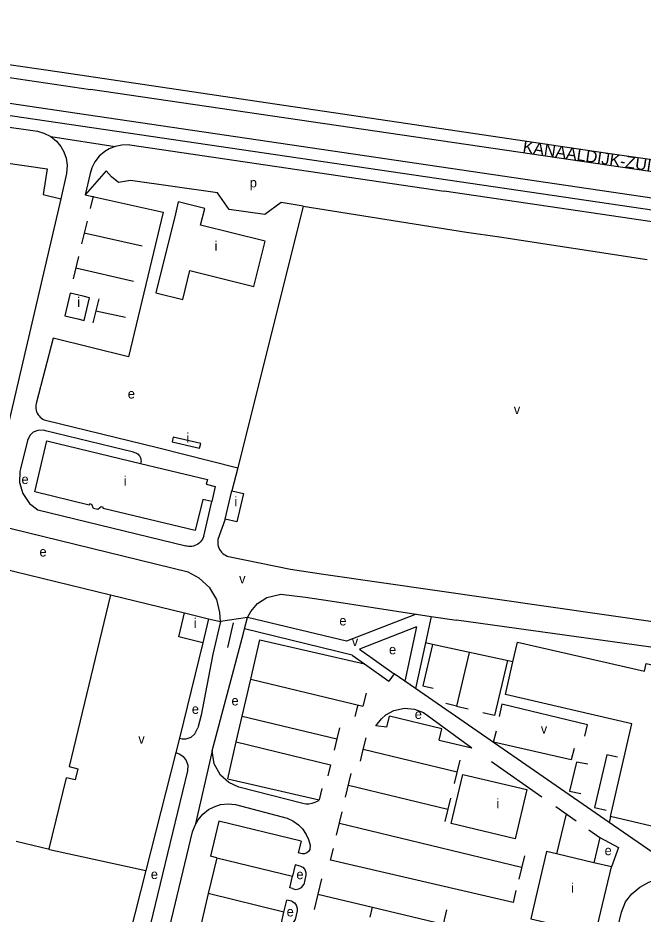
# Model space of a CAD drawing. Extents: x 162804 to 165059, y 381530 to 382901.
# Drawn here: x 163506.9 to 163766.6, y 382442.3 to 382814.6 of the extents above; entities that cross this region are included whole.
import ezdxf

# ---------------------------------------------------------------- set-up
doc = ezdxf.new("R2010")
doc.units = 0
for name, color, linetype in [('BLT_Basislijn', 7, 'Continuous'), ('BLT_Bebouwing', 7, 'Continuous'), ('BLT_Centroide', 7, 'Continuous'), ('BLT_Straatnaam', 7, 'Continuous'), ('BLT_Vlakafsluiter', 7, 'Continuous')]:
    doc.layers.add(name, color=color, linetype=linetype)

msp = doc.modelspace()

# ---------------------------------------------------------------- linework, layer by layer
at = {"layer": 'BLT_Basislijn'}
for p, q in [((163525.18, 382791.94), (163463.22, 382801.03)), ((163609.95, 382779.38), (163525.18, 382791.94)), ((163439.97, 382778.56), (163515.12, 382767.51)), ((163650.18, 382773.33), (163609.95, 382779.38)), ((163750, 382758.53), (163650.18, 382773.33)), ((163798.44, 382751.58), (163750, 382758.53)), ((163527.16, 382750), (163524.73, 382739.51)), ((163534.85, 382741.17), (163567.22, 382733.85)), ((163538.13, 382740.55), (163536.93, 382735.42)), ((163625.48, 382736.46), (163598.22, 382627.68)), ((163625.48, 382736.46), (163693.25, 382725.64)), ((163535.66, 382730.15), (163533.34, 382720.8)), ((163534.49, 382725.39), (163558.55, 382719.89)), ((163693.25, 382725.64), (163706.93, 382723.66)), ((163706.93, 382723.66), (163768.26, 382714.19)), ((163532.1, 382715.56), (163529.83, 382706.23)), ((163530.95, 382710.74), (163555, 382705.24)), ((163540.51, 382697.97), (163538.09, 382688.01)), ((163539.31, 382692.98), (163551.59, 382690.33)), ((163554.89, 382634.16), (163518.44, 382643.14)), ((163598.22, 382627.68), (163595.84, 382618.18)), ((163584.1, 382599.35), (163587.43, 382613.67)), ((163515.15, 382610.27), (163576.65, 382595.26)), ((163592.95, 382606.41), (163590.01, 382597.94)), ((163545.42, 382574.98), (163576.16, 382567.42)), ((163601.11, 382560.76), (163602.29, 382565.55)), ((163643.38, 382555.68), (163602.29, 382565.55)), ((163672.39, 382566.95), (163643.38, 382555.68)), ((163672.39, 382566.95), (163678.57, 382566)), ((163678.57, 382566), (163676.18, 382554.98)), ((163596.28, 382563.26), (163593.96, 382553.14)), ((163672.5, 382561.63), (163648.81, 382552.42)), ((163672.5, 382561.63), (163667.6, 382539.06)), ((163645.83, 382549.94), (163601.11, 382560.76)), ((163583.67, 382555.06), (163574.03, 382515.44)), ((163603.61, 382539.97), (163607.35, 382556.3)), ((163607.35, 382556.3), (163650.87, 382546.33)), ((163676.18, 382554.98), (163672.05, 382535.98)), ((163679.13, 382554.34), (163675.08, 382537.16)), ((163679.13, 382554.34), (163676.18, 382554.98)), ((163712.52, 382547.09), (163679.13, 382554.34)), ((163645.83, 382549.94), (163650.87, 382546.33)), ((163648.81, 382552.42), (163663.24, 382542.07)), ((163650.87, 382546.33), (163660.95, 382539.1)), ((163600.07, 382524.51), (163603.61, 382539.97)), ((163603.61, 382539.97), (163650.25, 382528.69)), ((163667.6, 382539.06), (163663.24, 382542.07)), ((163672.05, 382535.98), (163667.6, 382539.06)), ((163675.08, 382537.16), (163679.48, 382536.21)), ((163651.55, 382534.06), (163650.25, 382528.69)), ((163648.11, 382529.2), (163646.94, 382524.36)), ((163689.13, 382528.73), (163684.68, 382529.84)), ((163582.98, 382525.03), (163581.69, 382519.69)), ((163597.63, 382513.84), (163600.07, 382524.51)), ((163600.07, 382524.51), (163639.42, 382515.07)), ((163660.1, 382519.92), (163661.22, 382524.54)), ((163683.08, 382519.25), (163661.22, 382524.54)), ((163660.1, 382519.92), (163655.61, 382520.59)), ((163640.54, 382519.73), (163639.42, 382515.07)), ((163681.96, 382514.63), (163683.08, 382519.25)), ((163594.11, 382498.48), (163597.63, 382513.84)), ((163597.63, 382513.84), (163636.82, 382504.35)), ((163639.42, 382515.07), (163638.29, 382510.42)), ((163650.39, 382510.74), (163651.56, 382515.6)), ((163681.96, 382514.63), (163695.43, 382511.37)), ((163572.49, 382509.41), (163560.07, 382460.39)), ((163649.21, 382505.88), (163650.39, 382510.74)), ((163689.36, 382501.3), (163650.39, 382510.74)), ((163688.21, 382496.56), (163690.56, 382506.28)), ((163577.41, 382501.87), (163567, 382458.87)), ((163636.82, 382504.35), (163635.7, 382499.7)), ((163594.11, 382498.48), (163632.09, 382489.79)), ((163643.05, 382490.95), (163645.4, 382500.67)), ((163633.22, 382494.44), (163632.09, 382489.79)), ((163685.55, 382485.81), (163644.22, 382495.81)), ((163684.34, 382480.79), (163686.69, 382490.51)), ((163586.1, 382485.73), (163588.48, 382486.95)), ((163588.48, 382486.95), (163591.09, 382487.8)), ((163591.09, 382487.8), (163594.26, 382488.12)), ((163594.26, 382488.12), (163597.26, 382487.83)), ((163597.26, 382487.83), (163618.81, 382482.14)), ((163581.74, 382481.5), (163583.7, 382483.78)), ((163583.7, 382483.78), (163586.1, 382485.73)), ((163639.28, 382475.13), (163641.64, 382484.85)), ((163734.61, 382484.01), (163730.68, 382467.32)), ((163753.09, 382482.83), (163752.54, 382480.4)), ((163579.5, 382476.48), (163580.53, 382479.33)), ((163580.53, 382479.33), (163581.74, 382481.5)), ((163590.42, 382480.95), (163586.91, 382466.36)), ((163624.53, 382472.66), (163590.42, 382480.95)), ((163618.81, 382482.14), (163621.1, 382481.11)), ((163621.1, 382481.11), (163623.52, 382479.36)), ((163623.52, 382479.36), (163625.14, 382477.7)), ((163716.15, 382461.67), (163640.46, 382479.99)), ((163558.92, 382390.87), (163579.5, 382476.48)), ((163625.14, 382477.7), (163626.65, 382475.39)), ((163626.65, 382475.39), (163627.6, 382473.38)), ((163624.53, 382472.66), (163623.35, 382467.73)), ((163627.6, 382473.38), (163628.34, 382471.02)), ((163748.68, 382474.15), (163746.21, 382463.66)), ((163520.03, 382469.15), (163560.07, 382460.39)), ((163628.34, 382471.02), (163628.16, 382469.17)), ((163636.77, 382464.75), (163637.95, 382469.61)), ((163589.53, 382465.72), (163585.95, 382450.81)), ((163589.53, 382465.72), (163586.91, 382466.36)), ((163589.53, 382465.72), (163621.03, 382458.1)), ((163625.02, 382467.32), (163623.35, 382467.73)), ((163717.32, 382466.53), (163714.97, 382456.81)), ((163560.07, 382460.39), (163545.33, 382402.23)), ((163622.15, 382462.75), (163621.03, 382458.1)), ((163624.14, 382462.27), (163622.15, 382462.75)), ((163567, 382458.87), (163555.83, 382412.66)), ((163619.85, 382453.2), (163621.03, 382458.1)), ((163626.48, 382458.45), (163625.62, 382454.59)), ((163621.01, 382452.92), (163619.85, 382453.2)), ((163585.95, 382450.81), (163582.61, 382436.52)), ((163617.39, 382443.16), (163585.95, 382450.81)), ((163631.52, 382450.59), (163654.21, 382445.19)), ((163713.82, 382452.06), (163712.64, 382447.2)), ((163617.39, 382443.16), (163618.64, 382448.16)), ((163620.76, 382447.72), (163618.64, 382448.16)), ((163653.23, 382441.11), (163654.21, 382445.19))]:
    msp.add_line(p, q, dxfattribs=at)
for points in [[(163350, 382814.61), (163413.51, 382803.18), (163537.13, 382784.9)], [(163993.07, 382706.91), (163535.27, 382774.35), (163455.47, 382786.14), (163410.94, 382792.86), (163374.85, 382798.03), (163359.37, 382797.83)], [(164235.25, 382681.52), (163993.98, 382717.68), (163844.23, 382739.9), (163537.13, 382784.9)], [(163666.72, 382750), (163500, 382774.52)], [(163425.36, 382769.97), (163425.25, 382768.68), (163425.6, 382767.33), (163426.26, 382766.16), (163427.26, 382765.28), (163519.12, 382751.86), (163517.34, 382741.19), (163524.73, 382739.51)], [(163515.12, 382767.51), (163517.69, 382766.8), (163520.61, 382765.32)], [(163520.61, 382765.32), (163522.91, 382763.42), (163524.71, 382761.21), (163525.98, 382759.02), (163527, 382756.31), (163527.41, 382753.45), (163527.16, 382750)], [(163547.37, 382761.26), (163544.78, 382760.19), (163542.96, 382759.11), (163540.72, 382757.13), (163538.86, 382754.8), (163537.66, 382752.34), (163536.9, 382750), (163534.85, 382741.17)], [(163553.4, 382761.82), (163550.1, 382761.72), (163547.37, 382761.26)], [(163553.4, 382761.82), (163683.99, 382742.6)], [(163625.48, 382736.46), (163616.32, 382737.96), (163609.51, 382732.91), (163594.68, 382735.09), (163589.79, 382741.9), (163553.67, 382747.12), (163548.67, 382746.2), (163545.83, 382748.56), (163543.55, 382751.15), (163534.85, 382741.17)], [(163844.57, 382723.84), (163833.36, 382725.49), (163666.72, 382750)], [(163843.88, 382719.02), (163800.44, 382725.41), (163683.99, 382742.6)], [(163524.73, 382739.51), (163499.07, 382630.19), (163498.36, 382627.64), (163497.09, 382625.15)], [(163567.22, 382733.85), (163552.83, 382673.88), (163521.57, 382681.64), (163514.65, 382655.01)], [(163514.65, 382655.01), (163514.46, 382654.36), (163514.34, 382653.69), (163514.3, 382653.01), (163514.34, 382652.33), (163514.46, 382651.66), (163514.65, 382651), (163514.92, 382650.38), (163515.27, 382649.79), (163515.68, 382649.25), (163516.15, 382648.75), (163516.67, 382648.32), (163517.25, 382647.95), (163517.86, 382647.65), (163518.42, 382647.45)], [(163518.42, 382647.45), (163564.95, 382636.11), (163598.22, 382627.68)], [(163518.44, 382643.14), (163517.49, 382643.4), (163515.22, 382643.27), (163513.32, 382642.53), (163511.85, 382641.11), (163510.84, 382639.07), (163508.01, 382627.24), (163507.75, 382626.17), (163507.62, 382621.68), (163508.98, 382617.07), (163511.76, 382612.87), (163515.15, 382610.27)], [(163554.89, 382634.16), (163555.41, 382634.07), (163555.91, 382633.9), (163556.39, 382633.66), (163556.82, 382633.35), (163557.19, 382632.98), (163557.51, 382632.55), (163557.76, 382632.09), (163557.94, 382631.59), (163558.04, 382631.06), (163558.06, 382630.54), (163558, 382630.01), (163557.89, 382629.56)], [(163591.01, 382563.83), (163590.81, 382567.55), (163589.61, 382572.98), (163586.59, 382577.82), (163582.17, 382581.94), (163577.59, 382584.32), (163450.78, 382615.36)], [(163584.1, 382599.35), (163583.87, 382598.7), (163583.56, 382598.07), (163583.18, 382597.49), (163582.74, 382596.96), (163582.24, 382596.48), (163581.68, 382596.05), (163581.09, 382595.7), (163580.45, 382595.42), (163579.79, 382595.21), (163579.11, 382595.08), (163578.42, 382595.03), (163577.72, 382595.06), (163577.04, 382595.16), (163576.65, 382595.26)], [(163590.01, 382597.94), (163589.93, 382597.23), (163589.93, 382596.53), (163590.01, 382595.82), (163590.17, 382595.13), (163590.4, 382594.46), (163590.71, 382593.82), (163591.09, 382593.22), (163591.54, 382592.67), (163592.04, 382592.17), (163592.6, 382591.73), (163593.2, 382591.36), (163593.84, 382591.05), (163594.36, 382590.87)], [(163594.36, 382590.87), (163620.21, 382585.6), (163633.84, 382583.51), (163820.83, 382556.63)], [(163602.29, 382565.55), (163603.67, 382568.07), (163606.39, 382571.37), (163610.33, 382573.84), (163616.08, 382575.17), (163626.34, 382573.94), (163636.6, 382572.42), (163672.39, 382566.95)], [(163586.08, 382565.02), (163591.01, 382563.83)], [(163678.57, 382566), (163689.05, 382564.4)], [(163591.01, 382563.83), (163587.87, 382550.25), (163582.98, 382525.03)], [(163822.79, 382542.39), (163818.73, 382546.46), (163689.05, 382564.4)], [(163587.65, 382510.12), (163600.65, 382559.06), (163601.11, 382560.76)], [(163694.39, 382551.02), (163689.13, 382528.73), (163693.97, 382527.54)], [(163710.35, 382547.61), (163704.91, 382524.85), (163700.04, 382525.97)], [(163663.24, 382542.07), (163660.95, 382539.1)], [(163752.54, 382480.4), (163672.05, 382535.98)], [(163655.61, 382520.59), (163657.97, 382523.42), (163659.8, 382525.09), (163663.11, 382526.87), (163667.46, 382527.85), (163671.68, 382527.5), (163675.4, 382526.02), (163695.43, 382511.37)], [(163742.42, 382516.18), (163743.54, 382520.95), (163707.91, 382529.52), (163706.8, 382524.43)], [(163574.03, 382515.44), (163575.15, 382515.18), (163576.84, 382515.17), (163578.87, 382515.86), (163580.38, 382517.16), (163581.69, 382519.69)], [(163737.98, 382511.14), (163736.79, 382506.36), (163704.52, 382513.7), (163705.76, 382518.48)], [(163572.49, 382509.41), (163574.24, 382508.75), (163575.54, 382507.83), (163576.84, 382506.15), (163577.49, 382504.22), (163577.41, 382501.87)], [(163630.24, 382488.65), (163629.08, 382488.25), (163627.75, 382488.02), (163626.52, 382488.04), (163625.25, 382488.26), (163598.65, 382495.11), (163594.49, 382496.97), (163591.09, 382500), (163588.44, 382504.74), (163587.65, 382510.12)], [(163703.58, 382505.76), (163724.51, 382491.09)], [(163743.6, 382504.55), (163738.94, 382505.5), (163736.06, 382493.44), (163740.69, 382492.4)], [(163756.01, 382507.46), (163751.49, 382508.52), (163746.37, 382486.56), (163751.21, 382485.49)], [(163632.09, 382489.79), (163631.46, 382489.3), (163630.24, 382488.65)], [(163730.35, 382487), (163738.87, 382481.03)], [(163774.36, 382465.33), (163752.54, 382480.4)], [(163744.08, 382477.38), (163748.68, 382474.15)], [(163748.68, 382474.15), (163756.37, 382469.95), (163753.46, 382461.95)], [(163628.16, 382469.17), (163627.65, 382468.37), (163626.88, 382467.74), (163625.96, 382467.38), (163625.02, 382467.32)], [(163628.16, 382469.17), (163627.65, 382468.37), (163626.88, 382467.74), (163625.96, 382467.38), (163625.02, 382467.32)], [(163712.64, 382447.2), (163636.77, 382464.75)], [(163624.14, 382462.27), (163625.23, 382461.78), (163626.1, 382460.84), (163626.54, 382459.63), (163626.48, 382458.45)], [(163633.02, 382456.92), (163630.01, 382444.26)], [(163749.9, 382410.7), (163757.71, 382443.14), (163759.36, 382447.39), (163761.87, 382450.75), (163765.26, 382453.54), (163769.01, 382455.65), (163772.66, 382456.98), (163775.81, 382457.75), (163777.48, 382457.32), (163769.44, 382424.32), (163768.98, 382423.79), (163768.29, 382423.72), (163767.55, 382423.9), (163765.42, 382415.15), (163766.16, 382414.97), (163766.65, 382414.72), (163766.91, 382413.92), (163766.29, 382411.21), (163765.94, 382410.73), (163765.58, 382410.35), (163765.13, 382410.03), (163764.59, 382409.85), (163764.12, 382409.81), (163763.49, 382407.39)], [(163621.01, 382452.92), (163622.23, 382452.58), (163623.58, 382452.75), (163624.76, 382453.44), (163625.62, 382454.59)], [(163620.76, 382447.72), (163621.77, 382447.05), (163622.55, 382446.04), (163622.97, 382444.83), (163622.98, 382443.62)], [(163622.98, 382443.62), (163622.11, 382440.14), (163621.19, 382438.77), (163619.75, 382438.12), (163618.28, 382438.21), (163616.41, 382438.69), (163617.39, 382443.16)], [(163654.21, 382445.19), (163683.7, 382438.16), (163685.08, 382444.03)]]:
    msp.add_lwpolyline(points, dxfattribs=at)
at = {"layer": 'BLT_Bebouwing'}
for p, q in [((163592.95, 382606.41), (163595.84, 382618.18)), ((163500, 382585.97), (163545.42, 382574.98)), ((163686.95, 382479.89), (163691.77, 382500.33)), ((163691.77, 382500.33), (163718.31, 382494.08)), ((163718.31, 382494.08), (163713.49, 382473.63)), ((163713.49, 382473.63), (163686.95, 382479.89)), ((163520.03, 382469.15), (163506.23, 382472.49))]:
    msp.add_line(p, q, dxfattribs=at)
for points in [[(163573.55, 382738.17), (163572.33, 382733.28), (163564.19, 382700.44), (163575.4, 382697.66), (163578.37, 382709.64), (163604.98, 382703.04), (163609.64, 382721.85), (163582.81, 382728.5), (163584.53, 382735.45), (163573.55, 382738.17)], [(163528.68, 382700.28), (163526.38, 382690.89), (163531.83, 382689.57), (163534.45, 382688.94), (163536.7, 382698.32), (163534.08, 382698.96), (163528.68, 382700.28)], [(163571.43, 382640.47), (163570.98, 382638.55), (163582.41, 382635.91), (163582.86, 382637.83), (163571.43, 382640.47)], [(163513.91, 382617.73), (163519, 382638.96), (163557.89, 382629.56)], [(163557.89, 382629.56), (163585.67, 382622.85), (163585.13, 382620.86), (163588.9, 382619.89), (163587.43, 382613.67)], [(163587.43, 382613.67), (163583.68, 382614.58), (163580.56, 382601.65), (163542.33, 382610.84), (163542.44, 382611.29), (163541.46, 382611.53), (163540.12, 382610.41), (163538.35, 382610.81), (163537.66, 382612.45), (163536.66, 382612.69), (163536.56, 382612.25), (163513.91, 382617.73)], [(163595.84, 382618.18), (163600.68, 382616.99), (163597.79, 382605.22), (163592.95, 382606.41)], [(163545.42, 382574.98), (163528.16, 382503.57), (163531.87, 382502.67), (163530.75, 382498.05), (163527.04, 382498.95)], [(163583.67, 382555.06), (163573.75, 382557.45), (163576.16, 382567.42)], [(163576.16, 382567.42), (163586.08, 382565.02)], [(163586.08, 382565.02), (163583.67, 382555.06)], [(163712.52, 382547.09), (163714.42, 382555.34)], [(163714.42, 382555.34), (163767.2, 382543.22), (163767.93, 382546.38), (163789.89, 382541.32), (163774.87, 382477.79), (163753.09, 382482.83)], [(163753.09, 382482.83), (163761.99, 382521.41), (163709.4, 382533.56), (163712.52, 382547.09)], [(163520.03, 382469.15), (163520.06, 382469.39), (163519.91, 382469.42), (163527.04, 382498.95)], [(163730.68, 382467.32), (163726.55, 382468.29), (163721.11, 382445.25)], [(163746.21, 382463.66), (163730.68, 382467.32)], [(163753.46, 382461.95), (163746.21, 382463.66)], [(163746.89, 382434.06), (163753.46, 382461.95)], [(163721.11, 382445.25), (163719.97, 382440.41), (163746.89, 382434.06)]]:
    msp.add_lwpolyline(points, dxfattribs=at)
at = {"layer": 'BLT_Vlakafsluiter'}
for p, q in [((163520.61, 382765.32), (163547.37, 382761.26)), ((163602.29, 382565.55), (163591.01, 382563.83)), ((163574.03, 382515.44), (163572.49, 382509.41)), ((163587.65, 382510.12), (163580.53, 382479.33))]:
    msp.add_line(p, q, dxfattribs=at)

# ---------------------------------------------------------------- texts
at = {"layer": 'BLT_Centroide'}
for s, p in [('p', (163603.23, 382744.2)), ('i', (163588.59, 382717.91)), ('i', (163531.55, 382694.59)), ('e', (163552.55, 382656.52)), ('v', (163712.91, 382650.02)), ('i', (163576.91, 382638.19)), ('i', (163550.91, 382620.31)), ('e', (163508.39, 382620.98)), ('i', (163596.81, 382611.7)), ('e', (163515.86, 382590.88)), ('v', (163598.8, 382579.73)), ('i', (163579.92, 382561.23)), ('e', (163640.43, 382562.24)), ('v', (163645.6, 382553.65)), ('e', (163661.07, 382550.23)), ('e', (163595.62, 382529)), ('e', (163579.15, 382525.51)), ('e', (163671.76, 382523.4)), ('v', (163724.12, 382517.32)), ('v', (163556.92, 382513.16)), ('i', (163705.69, 382486.25)), ('e', (163750.62, 382466.78)), ('e', (163562.13, 382456.89)), ('e', (163622.59, 382456.82)), ('i', (163736.72, 382451.19)), ('e', (163618.55, 382441.36))]:
    msp.add_text(s, height=4, dxfattribs=at).set_placement(p)
at = {"layer": 'BLT_Straatnaam'}
msp.add_text('KANAALDIJK-ZUID', height=5, rotation=351.5211, dxfattribs=at).set_placement((163716.37, 382758.83))

doc.saveas('drawing.dxf')
